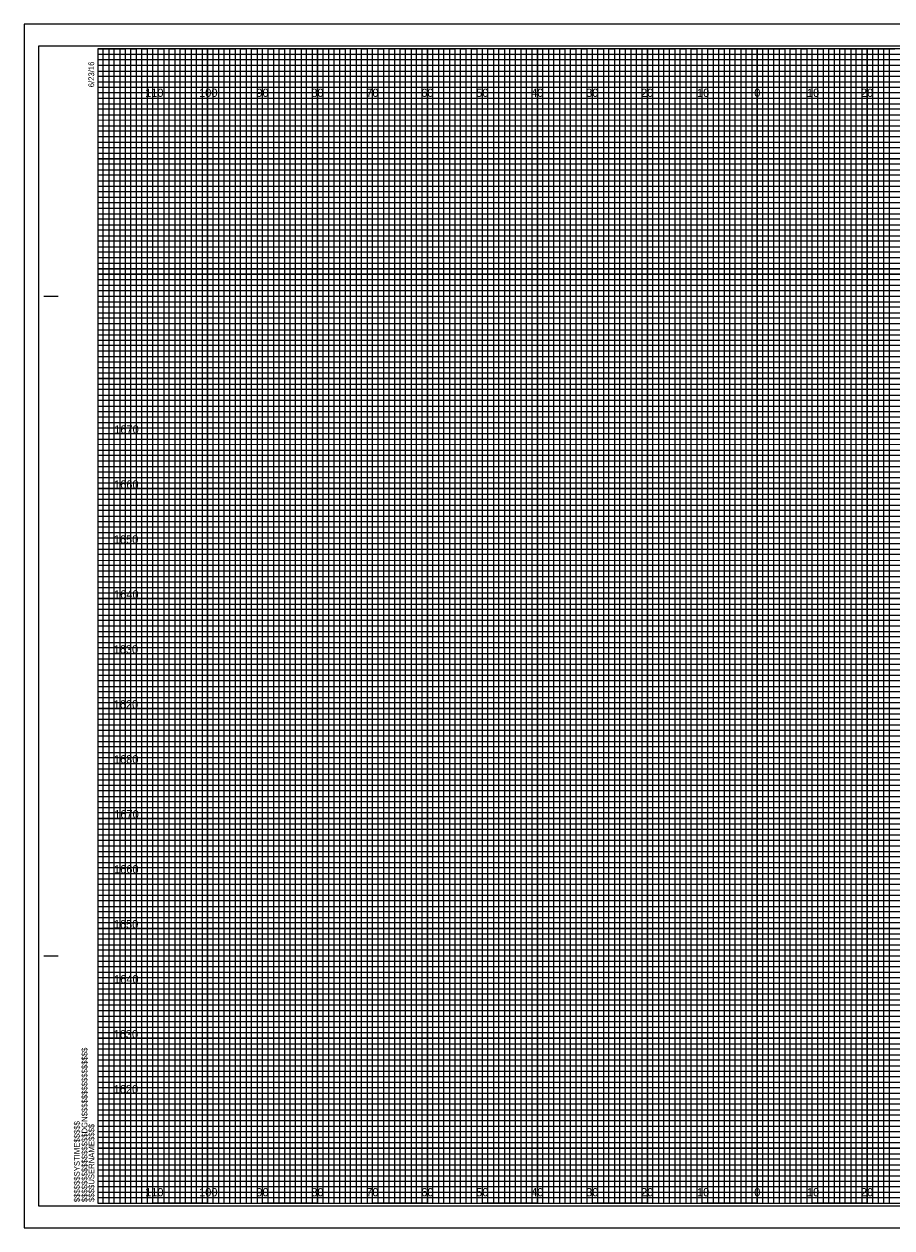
# Model space of a CAD drawing. Extents: x -13 to 1780, y -15 to 3284.
# Drawn here: x -13.4 to 144.5, y 215.5 to 434.5 of the extents above; entities that cross this region are included whole.
import ezdxf

# ---------------------------------------------------------------- set-up
doc = ezdxf.new("R2010")
doc.units = 0
for name, color, linetype in [('Prop Retaining Wall', 7, 'Continuous'), ('Prop SS Cut Line', 7, 'Continuous'), ('Prop SS Fill Line', 7, 'Continuous'), ('Prop SS Transition Line', 7, 'Continuous'), ('Prop XS Earthwork Shape', 7, 'Continuous'), ('Prop XS Noise Wall', 7, 'Continuous'), ('Prop XS Station Labels', 7, 'Continuous'), ('Raster_Level_0', 7, 'Continuous'), ('Scratch_Level_3', 7, 'Continuous'), ('Scratch_Level_7', 7, 'Continuous'), ('Typical Bridge Rail CELL', 7, 'Continuous')]:
    doc.layers.add(name, color=color, linetype=linetype)

msp = doc.modelspace()

# ---------------------------------------------------------------- linework, layer by layer
at = {"layer": 'Prop Retaining Wall'}
for p, q in [((-9.8, 385), (-7.3, 385)), ((-9.7, 385), (-7.2, 385)), ((-9.8, 265), (-7.3, 265)), ((-9.7, 265), (-7.2, 265)), ((0, 220), (0, 220)), ((0, 220), (0, 220)), ((0, 220), (0, 220)), ((0, 220), (0, 220)), ((0, 220), (0, 220)), ((0, 220), (0, 220)), ((0, 220), (0, 220))]:
    msp.add_line(p, q, dxfattribs=at)
msp.add_lwpolyline([(320, 430), (0, 430), (0, 220), (320, 220)], close=True, dxfattribs=at)
at = {"layer": 'Prop SS Cut Line'}
for points in [[(0, 430), (5, 430), (5, 220), (15, 220), (15, 430), (25, 430), (25, 220), (35, 220), (35, 430), (45, 430), (45, 220), (55, 220), (55, 430), (65, 430), (65, 220), (75, 220), (75, 430), (85, 430), (85, 220), (95, 220), (95, 430), (105, 430), (105, 220), (115, 220), (115, 430), (125, 430), (125, 220), (135, 220), (135, 430), (145, 430)], [(0, 425), (275, 425)], [(0, 405), (320, 405), (320, 415), (0, 415)], [(0, 385), (320, 385), (320, 395), (0, 395)], [(0, 365), (320, 365), (320, 375), (0, 375)], [(0, 345), (320, 345), (320, 355), (0, 355)], [(0, 325), (320, 325), (320, 335), (0, 335)], [(0, 305), (320, 305), (320, 315), (0, 315)], [(0, 285), (320, 285), (320, 295), (0, 295)], [(0, 265), (320, 265), (320, 275), (0, 275)], [(0, 245), (320, 245), (320, 255), (0, 255)], [(0, 225), (320, 225), (320, 235), (0, 235)]]:
    msp.add_lwpolyline(points, dxfattribs=at)
at = {"layer": 'Prop SS Fill Line'}
for p, q in [((10, 430), (0, 430)), ((10, 220), (10, 430)), ((30, 430), (20, 430)), ((20, 430), (20, 220)), ((30, 220), (30, 430)), ((50, 430), (40, 430)), ((40, 430), (40, 220)), ((50, 220), (50, 430)), ((70, 430), (60, 430)), ((60, 430), (60, 220)), ((70, 220), (70, 430)), ((90, 430), (80, 430)), ((80, 430), (80, 220)), ((90, 220), (90, 430)), ((110, 430), (100, 430)), ((100, 430), (100, 220)), ((110, 220), (110, 430)), ((130, 430), (120, 430)), ((120, 430), (120, 220)), ((130, 220), (130, 430)), ((150, 430), (140, 430)), ((140, 430), (140, 220)), ((20, 220), (10, 220)), ((40, 220), (30, 220)), ((60, 220), (50, 220)), ((80, 220), (70, 220)), ((100, 220), (90, 220)), ((120, 220), (110, 220)), ((140, 220), (130, 220))]:
    msp.add_line(p, q, dxfattribs=at)
for points in [[(0, 420), (320, 420), (320, 410), (0, 410)], [(0, 400), (320, 400), (320, 390), (0, 390)], [(0, 380), (320, 380), (320, 370), (0, 370)], [(0, 360), (320, 360), (320, 350), (0, 350)], [(0, 340), (320, 340), (320, 330), (0, 330)], [(0, 320), (320, 320), (320, 310), (0, 310)], [(0, 300), (320, 300), (320, 290), (0, 290)], [(0, 280), (320, 280), (320, 270), (0, 270)], [(0, 260), (320, 260), (320, 250), (0, 250)], [(0, 240), (320, 240), (320, 230), (0, 230)]]:
    msp.add_lwpolyline(points, dxfattribs=at)
at = {"layer": 'Prop SS Transition Line'}
for p, q in [((0, 429), (260, 429)), ((260, 427.98), (0, 427.98)), ((0, 427.98), (0, 427)), ((0, 427), (260, 427)), ((260, 425.89), (0, 425.89)), ((0, 425.89), (0, 424)), ((0, 424), (320, 424))]:
    msp.add_line(p, q, dxfattribs=at)
for points in [[(0, 423), (270, 423), (320, 423), (320, 422), (0, 422)], [(0, 421), (320, 421), (320, 419), (0, 419)], [(0, 418), (320, 418), (320, 417), (0, 416.98)], [(0, 416), (320, 416), (320, 414), (0, 414)], [(0, 413), (320, 413), (320, 412), (0, 412)], [(0, 411), (320, 411), (320, 409), (0, 409)], [(0, 408), (320, 408), (320, 407), (0, 407)], [(0, 406), (320, 406), (320, 404), (0, 404)], [(0, 403), (320, 403), (320, 402), (0, 402)], [(0, 401), (320, 401), (320, 399), (0, 399)], [(0, 398), (320, 398), (320, 397), (0, 397)], [(0, 396), (320, 396), (320, 393.95), (320, 393), (320, 392), (0, 392)], [(0, 394), (320, 394), (320, 393), (0, 393)], [(0, 391), (320, 391), (320, 389), (0, 389.03)], [(0, 389.03), (320, 389), (320, 388), (0, 388)], [(0, 387), (320, 387), (320, 386), (0, 386)], [(0, 384), (320, 384), (320, 383), (0, 383)], [(0, 382), (320, 382), (320, 381), (0, 381)], [(-0.07, 378.89), (320, 378.89), (320, 377.88), (-0.07, 377.88)], [(0, 377), (320, 377), (320, 376), (0, 376)], [(0, 374), (320, 374), (320, 373), (0, 373)], [(0, 372), (320, 372), (320, 371), (0, 371)], [(0, 369), (320, 369), (320, 368), (0, 368)], [(0, 367), (320, 367), (320, 366), (0, 366)], [(0, 364), (320, 364), (320, 363), (0, 363)], [(0, 362), (320, 362), (320, 361), (0, 361)], [(0, 359), (320, 359), (319.99, 357.98), (0, 358)], [(0, 357), (320, 357), (320, 356), (0, 356)], [(0, 354), (320, 354), (320, 353), (0, 353)], [(0, 352), (320, 352), (320, 351), (0, 351)], [(0, 349), (320, 349), (320, 348), (0, 348)], [(0, 347), (320, 347), (320, 346), (0, 346)], [(0, 344), (320, 344), (320, 343), (0, 343)], [(0, 342), (320, 342), (320, 341), (0, 341)], [(0, 339), (320, 339), (320, 338), (0, 338)], [(0, 336.99), (320.07, 336.91), (320, 336), (0, 336)], [(0, 334), (320, 334), (320, 333), (0, 333)], [(0, 332), (320, 332), (320, 331), (0, 331)], [(0, 329), (320, 329), (320, 328), (0, 328)], [(0, 327), (320, 327), (320, 326), (0, 326)], [(0, 324), (320, 324), (320, 323), (0, 323)], [(0, 322), (320, 322), (320, 321), (0, 321)], [(0, 319), (320, 319), (320, 318), (0, 318)], [(0, 317), (320, 317), (320, 316), (0, 316)], [(0, 314), (320, 314), (320, 313), (0, 313)], [(0, 312), (320, 312), (320, 311), (0, 311)], [(0, 309), (320, 309), (320, 308), (0, 308)], [(0, 307), (320, 307), (320, 306), (0, 306)], [(0, 304), (320, 304), (320, 303), (0, 303)], [(0, 302), (320, 302), (320, 301), (0, 301)], [(0, 299), (320, 299), (319.99, 297.98), (0, 298)], [(0, 297), (320, 297), (320, 296), (0, 296)], [(0, 294), (320, 294), (320, 293), (0, 293)], [(0, 292), (320, 292), (320, 291), (0, 291)], [(0, 289), (320, 289), (320, 288), (0, 288)], [(0, 287), (320, 287), (320, 286), (0, 286)], [(0, 284), (320, 284), (320, 283), (0, 283)], [(0, 282), (320, 282), (320, 281), (0, 281)], [(0, 279), (320, 279), (320, 278), (0, 278)], [(0, 276.99), (320.07, 276.91), (320, 276), (0, 276)], [(0, 274), (320, 274), (320, 273), (0, 273)], [(0, 272), (320, 272), (320, 271), (0, 271)], [(0, 269), (320, 269), (320, 268), (0, 268)], [(0, 267), (320, 267), (320, 266), (0, 266)], [(0, 264), (320, 264), (320, 263), (0, 263)], [(0, 262), (320, 262), (320, 261), (0, 261)], [(0, 259), (320, 259), (320, 258), (0, 258)], [(0, 257), (320, 257), (320, 256), (0, 256)], [(0, 254), (320, 254), (320, 253), (0, 253)], [(0, 252), (320, 252), (320, 251), (0, 251)], [(0, 249), (320, 249), (320, 248), (0, 248)], [(0, 247), (320, 247), (320, 246), (0, 246)], [(0, 244), (320, 244), (320, 243), (0, 243)], [(0, 242), (320, 242), (320, 241), (0, 241)], [(0, 239), (320, 239), (320, 238), (0, 238)], [(0, 237), (320, 237), (320, 236), (0, 236)], [(0, 234), (320, 234), (320, 233), (0, 233)], [(0, 232), (320, 232), (320, 231), (0, 231)], [(0, 229), (320, 229), (320, 228), (0, 228)], [(0, 227), (320, 227), (320, 226), (0, 226)], [(0, 224), (320, 224), (320, 223), (0, 223)], [(0, 222), (320, 222), (320, 221), (0, 221)]]:
    msp.add_lwpolyline(points, dxfattribs=at)
at = {"layer": 'Prop XS Earthwork Shape'}
msp.add_lwpolyline([(-13.4, 215.5), (323.3, 215.5), (323.3, 434.5), (-13.4, 434.5)], close=True, dxfattribs=at)
at = {"layer": 'Prop XS Noise Wall'}
for p, q in [((10, 220), (10, 430)), ((20, 220), (20, 430)), ((30, 220), (30, 430)), ((40, 220), (40, 430)), ((50, 220), (50, 430)), ((60, 220), (60, 430)), ((70, 220), (70, 430)), ((80, 220), (80, 430)), ((90, 220), (90, 430)), ((100, 220), (100, 430)), ((110, 220), (110, 430)), ((120, 220), (120, 430)), ((130, 220), (130, 430)), ((140, 220), (140, 430)), ((0, 420), (320, 420)), ((0, 410), (320, 410)), ((0, 400), (320, 400)), ((0, 390), (320, 390)), ((0, 380), (320, 380)), ((0, 370), (320, 370)), ((0, 360), (320, 360)), ((0, 350), (320, 350)), ((0, 340), (320, 340)), ((0, 330), (320, 330)), ((0, 320), (320, 320)), ((0, 310), (320, 310)), ((0, 300), (320, 300)), ((0, 290), (320, 290)), ((0, 280), (320, 280)), ((0, 270), (320, 270)), ((0, 260), (320, 260)), ((0, 250), (320, 250)), ((0, 240), (320, 240)), ((0, 230), (320, 230))]:
    msp.add_line(p, q, dxfattribs=at)
at = {"layer": 'Prop XS Station Labels'}
for p, q in [((323.3, 434.5), (-13.4, 434.5)), ((-13.4, 434.5), (-13.4, 215.5)), ((-13.4, 215.5), (323.3, 215.5))]:
    msp.add_line(p, q, dxfattribs=at)
at = {"layer": 'Scratch_Level_7'}
msp.add_lwpolyline([(-10.8, 219.5), (322.4, 219.5), (322.4, 430.5), (-10.8, 430.5)], close=True, dxfattribs=at)
at = {"layer": 'Typical Bridge Rail CELL'}
for points in [[(0, 220), (1, 220), (1, 430), (2, 430), (2, 220)], [(2, 220), (3, 220), (3, 430), (4, 430), (4, 220)], [(5, 220), (6, 220), (6, 430), (7, 430), (7, 220)], [(7, 220), (8, 220), (8, 430), (9, 430), (9, 220)], [(10, 220), (11, 220), (11, 430), (12, 430), (12, 220)], [(12, 220), (13, 220), (13, 430), (14, 430), (14, 220)], [(15, 220), (16, 220), (16, 430), (17, 430), (17, 220)], [(17, 220), (18, 220), (18, 430), (19, 430), (19, 220)], [(20, 220), (21, 220), (21, 430), (22, 430), (22, 220)], [(22, 220), (23, 220), (23, 430), (24, 430), (24, 220)], [(25, 220), (26, 220), (26, 430), (27, 430), (27, 220)], [(27, 220), (28, 220), (28, 430), (29, 430), (29, 220)], [(30, 220), (31, 220), (31, 430), (32, 430), (32, 220)], [(32, 220), (33, 220), (33, 430), (34, 430), (34, 220)], [(35, 220), (36, 220), (36, 430), (37, 430), (37, 220)], [(37, 220), (38, 220), (38, 430), (39, 430), (39, 220)], [(40, 220), (41, 220), (41, 430), (42, 430), (42, 220)], [(42, 220), (43, 220), (43, 430), (44, 430), (44, 220)], [(45, 220), (46, 220), (46, 430), (47, 430), (47, 220)], [(47, 220), (48, 220), (48, 430), (49, 430), (49, 220)], [(50, 220), (51, 220), (51, 430), (52, 430), (52, 220)], [(52, 220), (53, 220), (53, 430), (54, 430), (54, 220)], [(55, 220), (56, 220), (56, 430), (57, 430), (57, 220)], [(57, 220), (58, 220), (58, 430), (59, 430), (59, 220)], [(60, 220), (61, 220), (61, 430), (62, 430), (62, 220)], [(62, 220), (63, 220), (63, 430), (64, 430), (64, 220)], [(65, 220), (66, 220), (66, 430), (67, 430), (67, 220)], [(67, 220), (68, 220), (68, 430), (69, 430), (69, 220)], [(70, 220), (71, 220), (71, 430), (72, 430), (72, 220)], [(72, 220), (73, 220), (73, 430), (74, 430), (74, 220)], [(75, 220), (76, 220), (76, 430), (77, 430), (77, 220)], [(77, 220), (78, 220), (78, 430), (79, 430), (79, 220)], [(80, 220), (81, 220), (81, 430), (82, 430), (82, 220)], [(82, 220), (83, 220), (83, 430), (84, 430), (84, 220)], [(85, 220), (86, 220), (86, 430), (87, 430), (87, 220)], [(87, 220), (88, 220), (88, 430), (89, 430), (89, 220)], [(90, 220), (91, 220), (91, 430), (92, 430), (92, 220)], [(92, 220), (93, 220), (93, 430), (94, 430), (94, 220)], [(95, 220), (96, 220), (96, 430), (97, 430), (97, 220)], [(97, 220), (98, 220), (98, 430), (99, 430), (99, 220)], [(100, 220), (101, 220), (101, 430), (102, 430), (102, 220)], [(102, 220), (103, 220), (103, 430), (104, 430), (104, 220)], [(105, 220), (106, 220), (106, 430), (107, 430), (107, 220)], [(107, 220), (108, 220), (108, 430), (109, 430), (109, 220)], [(110, 220), (111, 220), (111, 430), (112, 430), (112, 220)], [(112, 220), (113, 220), (113, 430), (114, 430), (114, 220)], [(115, 220), (116, 220), (116, 430), (117, 430), (117, 220)], [(117, 220), (118, 220), (118, 430), (119, 430), (119, 220)], [(120, 220), (121, 220), (121, 430), (122, 430), (122, 220)], [(122, 220), (123, 220), (123, 430), (124, 430), (124, 220)], [(125, 220), (126, 220), (126, 430), (127, 430), (127, 220)], [(127, 220), (128, 220), (128, 430), (129, 430), (129, 220)], [(130, 220), (131, 220), (131, 430), (132, 430), (132, 220)], [(132, 220), (133, 220), (133, 430), (134, 430), (134, 220)], [(135, 220), (136, 220), (136, 430), (137, 430), (137, 220)], [(137, 220), (138, 220), (138, 430), (139, 430), (139, 220)], [(140, 220), (141, 220), (141, 430), (142, 430), (142, 220)], [(142, 220), (143, 220), (143, 430), (144, 430), (144, 220)]]:
    msp.add_lwpolyline(points, dxfattribs=at)

# ---------------------------------------------------------------- texts
at = {"layer": 'Prop Retaining Wall'}
for s, p in [('6/23/16', (-0.65, 423)), ('$$$$$$$$$$$$$$$$DGN$$$$$$$$$$$$$$$$', (-1.88, 220.18)), ('$$$$$$SYSTIME$$$$$', (-3.26, 220.18)), ('$$$$USERNAME$$$$', (-0.62, 220.23))]:
    msp.add_text(s, height=1.05, rotation=90, dxfattribs=at).set_placement(p)
at = {"layer": 'Raster_Level_0'}
for s, p in [('110', (8.62, 421.25)), ('100', (18.44, 421.25)), ('90', (28.86, 421.25)), ('80', (38.86, 421.25)), ('70', (48.86, 421.25)), ('60', (58.86, 421.25)), ('50', (68.86, 421.25)), ('40', (78.86, 421.25)), ('30', (88.86, 421.25)), ('20', (98.86, 421.25)), ('10', (109.04, 421.25)), ('0', (119.45, 421.25)), ('0', (119.45, 421.25)), ('10', (129.04, 421.25)), ('20', (138.86, 421.25)), ('110', (8.62, 221.25)), ('100', (18.44, 221.25)), ('90', (28.86, 221.25)), ('80', (38.86, 221.25)), ('70', (48.86, 221.25)), ('60', (58.86, 221.25)), ('50', (68.86, 221.25)), ('40', (78.86, 221.25)), ('30', (88.86, 221.25)), ('20', (98.86, 221.25)), ('10', (109.04, 221.25)), ('0', (119.45, 221.25)), ('0', (119.45, 221.25)), ('10', (129.04, 221.25)), ('20', (138.86, 221.25))]:
    msp.add_text(s, height=1.5, dxfattribs=at).set_placement(p)
at = {"layer": 'Scratch_Level_3'}
for s, p in [('1670', (3, 360)), ('1660', (2.97, 350)), ('1650', (2.92, 340)), ('1640', (2.97, 330)), ('1630', (2.89, 320)), ('1620', (2.9, 310)), ('1680', (2.95, 300)), ('1670', (3, 290)), ('1660', (2.97, 280)), ('1650', (2.92, 270)), ('1640', (2.97, 260)), ('1630', (2.89, 250)), ('1620', (2.9, 240))]:
    msp.add_text(s, height=1.5, dxfattribs=at).set_placement(p)

doc.saveas('drawing.dxf')
